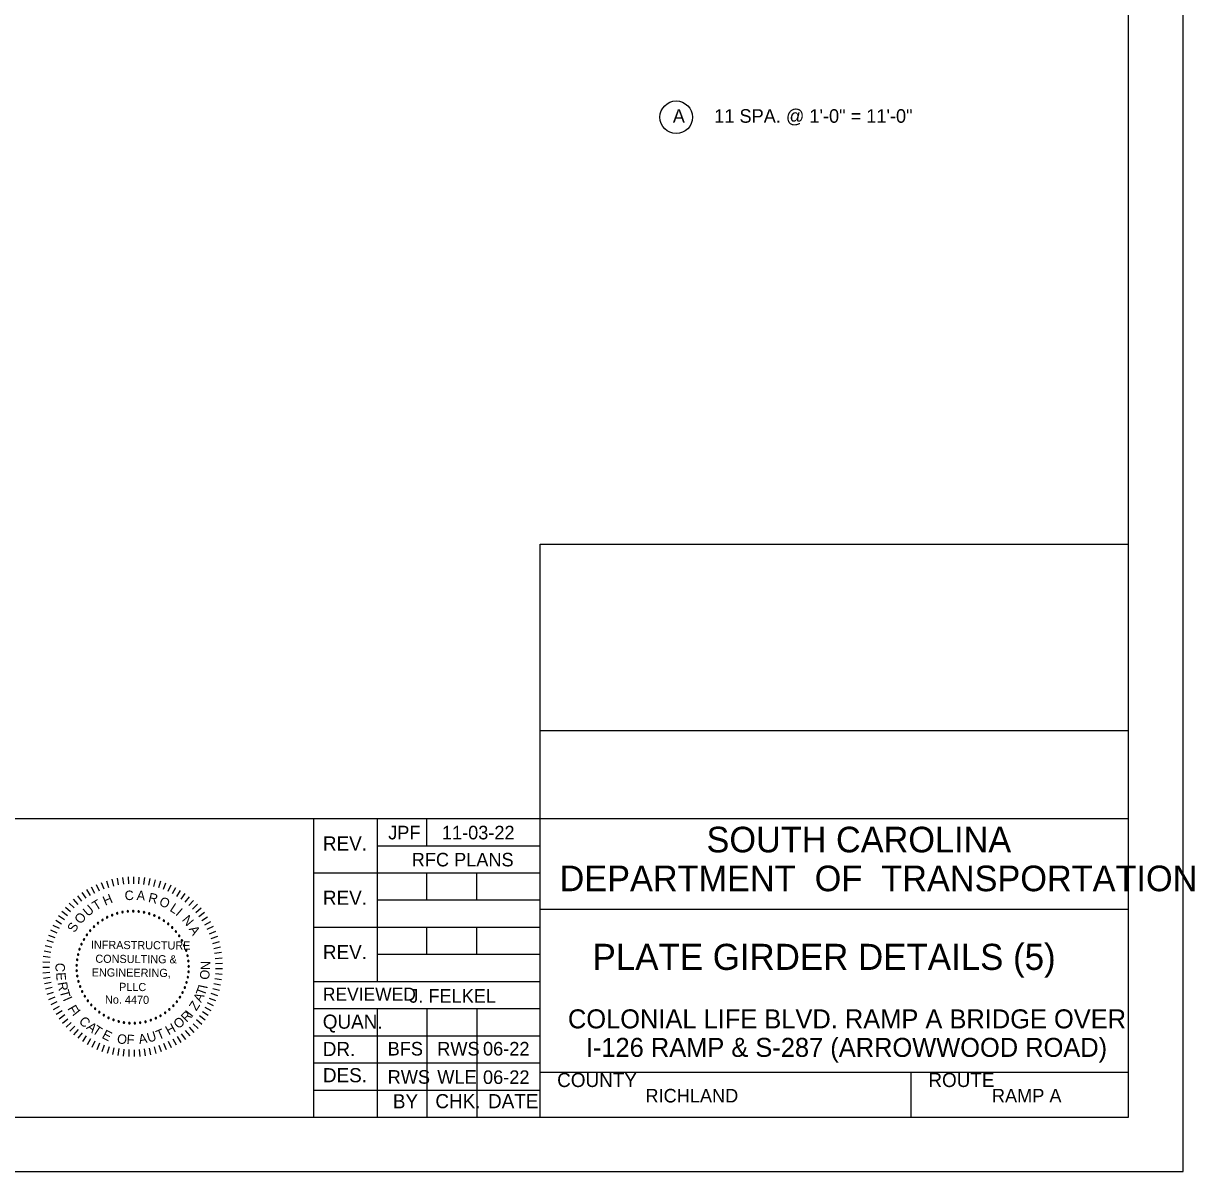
# Model space of a CAD drawing. Extents: x -383 to 14, y -392 to -94.
# Drawn here: x -203.87 to -160.75, y -187.49 to -145.21 of the extents above; entities that cross this region are included whole.
import ezdxf

# ---------------------------------------------------------------- set-up
doc = ezdxf.new("R2010")
doc.units = 0
for name, color, linetype in [('BR_BORDER LINES', 7, 'Continuous'), ('BR_TEXT', 7, 'Continuous'), ('Level 31', 7, 'Continuous')]:
    doc.layers.add(name, color=color, linetype=linetype)

msp = doc.modelspace()

# ---------------------------------------------------------------- linework, layer by layer
at = {"layer": 'BR_BORDER LINES'}
for p, q in [((-163.178, -185.489), (-163.178, -101.489)), ((-184.846, -185.489), (-184.846, -164.383)), ((-184.846, -164.383), (-163.178, -164.383)), ((-184.845, -171.242), (-163.178, -171.242)), ((-214.64, -174.489), (-193.18, -174.489)), ((-193.18, -185.489), (-193.18, -174.489)), ((-193.18, -174.489), (-163.178, -174.489)), ((-190.846, -174.489), (-190.846, -180.489)), ((-189.013, -175.489), (-189.013, -174.489)), ((-190.846, -175.489), (-184.846, -175.489)), ((-193.18, -176.489), (-184.846, -176.489)), ((-189.013, -177.489), (-189.013, -176.489)), ((-187.179, -177.489), (-187.179, -176.489)), ((-190.846, -177.489), (-184.846, -177.489)), ((-184.846, -177.822), (-184.846, -177.822)), ((-184.846, -177.823), (-163.178, -177.823)), ((-193.18, -178.489), (-184.846, -178.489)), ((-189.013, -179.489), (-189.013, -178.489)), ((-187.179, -179.489), (-187.179, -178.489)), ((-190.846, -179.489), (-184.846, -179.489)), ((-193.18, -180.489), (-184.846, -180.489)), ((-193.18, -181.489), (-184.846, -181.489)), ((-190.846, -181.489), (-190.846, -185.489)), ((-189.013, -181.489), (-189.013, -185.489)), ((-187.179, -181.489), (-187.179, -185.489)), ((-193.18, -182.489), (-184.846, -182.489)), ((-193.18, -183.489), (-184.846, -183.489)), ((-184.846, -183.823), (-163.178, -183.823)), ((-184.456, -183.823), (-163.178, -183.823)), ((-171.179, -185.489), (-171.179, -183.823)), ((-193.18, -184.489), (-184.846, -184.489)), ((-297.843, -185.489), (-163.178, -185.489))]:
    msp.add_line(p, q, dxfattribs=at)
at = {"layer": 'BR_TEXT'}
for p, q in [((-200.615, -176.726), (-200.555, -176.974)), ((-200.417, -176.685), (-200.373, -176.936)), ((-200.217, -176.656), (-200.188, -176.909)), ((-200.016, -176.64), (-200.002, -176.894)), ((-199.814, -176.636), (-199.816, -176.89)), ((-199.612, -176.644), (-199.63, -176.898)), ((-199.411, -176.664), (-199.444, -176.917)), ((-199.212, -176.697), (-199.26, -176.947)), ((-199.015, -176.741), (-199.079, -176.988)), ((-201.546, -177.106), (-201.415, -177.324)), ((-201.37, -177.007), (-201.252, -177.233)), ((-201.188, -176.92), (-201.084, -177.153)), ((-201.001, -176.844), (-200.912, -177.082)), ((-200.81, -176.779), (-200.735, -177.023)), ((-198.821, -176.798), (-198.9, -177.04)), ((-198.631, -176.866), (-198.724, -177.103)), ((-198.446, -176.946), (-198.553, -177.177)), ((-198.265, -177.037), (-198.387, -177.261)), ((-198.091, -177.139), (-198.226, -177.355)), ((-202.182, -177.601), (-202.002, -177.781)), ((-202.035, -177.463), (-201.866, -177.654)), ((-201.879, -177.334), (-201.723, -177.535)), ((-201.716, -177.215), (-201.572, -177.425)), ((-197.923, -177.251), (-198.071, -177.458)), ((-197.762, -177.373), (-197.922, -177.571)), ((-197.609, -177.505), (-197.781, -177.693)), ((-202.57, -178.065), (-202.36, -178.21)), ((-202.45, -177.903), (-202.25, -178.06)), ((-202.321, -177.748), (-202.13, -177.917)), ((-197.464, -177.646), (-197.647, -177.823)), ((-197.329, -177.795), (-197.522, -177.961)), ((-197.202, -177.952), (-197.405, -178.106)), ((-202.779, -178.411), (-202.553, -178.529)), ((-202.679, -178.235), (-202.461, -178.366)), ((-197.086, -178.117), (-197.298, -178.258)), ((-196.979, -178.289), (-197.199, -178.417)), ((-196.883, -178.467), (-197.111, -178.581)), ((-202.944, -178.779), (-202.705, -178.869)), ((-202.867, -178.593), (-202.634, -178.696)), ((-196.799, -178.65), (-197.033, -178.75)), ((-196.725, -178.838), (-196.965, -178.924)), ((-203.104, -179.363), (-202.853, -179.407)), ((-203.063, -179.165), (-202.815, -179.225)), ((-203.009, -178.97), (-202.766, -179.045)), ((-196.664, -179.03), (-196.908, -179.101)), ((-196.614, -179.226), (-196.862, -179.282)), ((-203.151, -179.764), (-202.897, -179.777)), ((-203.134, -179.562), (-202.881, -179.592)), ((-196.576, -179.424), (-196.827, -179.465)), ((-196.55, -179.625), (-196.804, -179.65)), ((-203.156, -179.965), (-202.901, -179.964)), ((-203.149, -180.167), (-202.895, -180.15)), ((-196.547, -180.23), (-196.8, -180.208)), ((-196.537, -179.826), (-196.791, -179.836)), ((-196.535, -180.028), (-196.79, -180.022)), ((-203.129, -180.368), (-202.877, -180.335)), ((-203.097, -180.568), (-202.847, -180.52)), ((-196.606, -180.629), (-196.855, -180.577)), ((-196.57, -180.43), (-196.822, -180.393)), ((-203.053, -180.765), (-202.807, -180.701)), ((-202.997, -180.959), (-202.755, -180.881)), ((-202.93, -181.149), (-202.693, -181.056)), ((-196.713, -181.018), (-196.954, -180.936)), ((-196.653, -180.825), (-196.899, -180.758)), ((-202.851, -181.335), (-202.62, -181.228)), ((-202.761, -181.516), (-202.536, -181.395)), ((-196.96, -181.57), (-197.182, -181.446)), ((-196.867, -181.392), (-197.096, -181.281)), ((-196.784, -181.207), (-197.02, -181.111)), ((-202.66, -181.69), (-202.443, -181.556)), ((-202.548, -181.859), (-202.34, -181.711)), ((-202.426, -182.02), (-202.228, -181.86)), ((-197.304, -182.068), (-197.5, -181.905)), ((-197.179, -181.91), (-197.385, -181.759)), ((-197.065, -181.743), (-197.279, -181.605)), ((-202.295, -182.173), (-202.107, -182.002)), ((-202.155, -182.319), (-201.977, -182.136)), ((-202.006, -182.455), (-201.84, -182.262)), ((-201.849, -182.582), (-201.695, -182.379)), ((-197.733, -182.495), (-197.895, -182.3)), ((-197.581, -182.362), (-197.756, -182.176)), ((-197.438, -182.219), (-197.623, -182.045)), ((-201.685, -182.699), (-201.543, -182.487)), ((-201.513, -182.806), (-201.385, -182.586)), ((-201.336, -182.903), (-201.221, -182.675)), ((-201.153, -182.988), (-201.053, -182.754)), ((-198.596, -183.012), (-198.692, -182.777)), ((-198.411, -182.93), (-198.522, -182.701)), ((-198.232, -182.837), (-198.356, -182.615)), ((-198.059, -182.734), (-198.196, -182.519)), ((-197.892, -182.62), (-198.042, -182.414)), ((-200.965, -183.062), (-200.879, -182.822)), ((-200.773, -183.125), (-200.702, -182.88)), ((-200.577, -183.175), (-200.521, -182.927)), ((-200.379, -183.214), (-200.338, -182.962)), ((-200.179, -183.24), (-200.154, -182.987)), ((-199.978, -183.254), (-199.968, -183)), ((-199.776, -183.256), (-199.781, -183.002)), ((-199.574, -183.246), (-199.595, -182.992)), ((-199.373, -183.223), (-199.41, -182.971)), ((-199.174, -183.188), (-199.226, -182.939)), ((-198.978, -183.142), (-199.045, -182.896)), ((-198.785, -183.083), (-198.867, -182.842))]:
    msp.add_line(p, q, dxfattribs=at)
msp.add_circle((-179.834, -148.668), 0.6, dxfattribs=at)
for centre, start, end in [((-200.603, -178.045), 21.6807, 201.6807), ((-200.603, -178.045), 201.6807, 21.6807), ((-200.414, -177.98), 16.1422, 196.1422), ((-200.414, -177.98), 196.1422, 16.1422), ((-200.22, -177.935), 10.6038, 190.6038), ((-200.22, -177.935), 190.6038, 10.6038), ((-200.023, -177.908), 5.0653, 185.0653), ((-200.023, -177.908), 185.0653, 5.0653), ((-199.824, -177.9), 359.5268, 179.5268), ((-199.824, -177.9), 179.5268, 359.5268), ((-199.625, -177.912), 353.9884, 173.9884), ((-199.625, -177.912), 173.9884, 353.9884), ((-199.428, -177.943), 168.4499, 348.4499), ((-199.428, -177.943), 348.4499, 168.4499), ((-199.235, -177.992), 162.9114, 342.9114), ((-199.235, -177.992), 342.9114, 162.9114), ((-199.047, -178.06), 157.373, 337.373), ((-199.047, -178.06), 337.373, 157.373), ((-201.27, -178.472), 43.8345, 223.8345), ((-201.27, -178.472), 223.8345, 43.8345), ((-201.12, -178.341), 38.2961, 218.2961), ((-201.12, -178.341), 218.2961, 38.2961), ((-200.957, -178.226), 32.7576, 212.7576), ((-200.957, -178.226), 212.7576, 32.7576), ((-200.785, -178.127), 27.2191, 207.2191), ((-200.785, -178.127), 207.2191, 27.2191), ((-198.867, -178.146), 151.8345, 331.8345), ((-198.867, -178.146), 331.8345, 151.8345), ((-198.697, -178.249), 146.2961, 326.2961), ((-198.697, -178.249), 326.2961, 146.2961), ((-198.537, -178.368), 140.7576, 320.7576), ((-198.537, -178.368), 320.7576, 140.7576), ((-198.389, -178.502), 135.2191, 315.2191), ((-198.389, -178.502), 315.2191, 135.2191), ((-201.637, -178.942), 60.4499, 240.4499), ((-201.637, -178.942), 240.4499, 60.4499), ((-201.53, -178.774), 54.9114, 234.9114), ((-201.53, -178.774), 234.9114, 54.9114), ((-201.408, -178.617), 49.373, 229.373), ((-201.408, -178.617), 229.373, 49.373), ((-198.255, -178.649), 129.6807, 309.6807), ((-198.255, -178.649), 309.6807, 129.6807), ((-198.135, -178.809), 124.1422, 304.1422), ((-198.135, -178.809), 304.1422, 124.1422), ((-201.8, -179.305), 71.5268, 251.5268), ((-201.8, -179.305), 251.5268, 71.5268), ((-201.727, -179.12), 65.9884, 245.9884), ((-201.727, -179.12), 245.9884, 65.9884), ((-198.032, -178.979), 118.6038, 298.6038), ((-198.032, -178.979), 298.6038, 118.6038), ((-197.945, -179.159), 113.0653, 293.0653), ((-197.945, -179.159), 293.0653, 113.0653), ((-197.876, -179.346), 107.5268, 287.5268), ((-197.876, -179.346), 287.5268, 107.5268), ((-201.89, -179.693), 82.6038, 262.6038), ((-201.89, -179.693), 262.6038, 82.6038), ((-201.854, -179.497), 77.0653, 257.0653), ((-201.854, -179.497), 257.0653, 77.0653), ((-197.826, -179.538), 101.9884, 281.9884), ((-197.826, -179.538), 281.9884, 101.9884), ((-197.795, -179.735), 96.4499, 276.4499), ((-197.795, -179.735), 276.4499, 96.4499), ((-201.906, -179.892), 88.1422, 268.1422), ((-201.904, -180.091), 93.6807, 273.6807), ((-201.906, -179.892), 268.1422, 88.1422), ((-201.904, -180.091), 273.6807, 93.6807), ((-197.789, -180.133), 85.373, 265.373), ((-197.782, -179.934), 90.9114, 270.9114), ((-197.789, -180.133), 265.373, 85.373), ((-197.782, -179.934), 270.9114, 90.9114), ((-201.882, -180.289), 99.2191, 279.2191), ((-201.882, -180.289), 279.2191, 99.2191), ((-201.841, -180.484), 104.7576, 284.7576), ((-201.841, -180.484), 284.7576, 104.7576), ((-201.781, -180.675), 110.2961, 290.2961), ((-201.781, -180.675), 290.2961, 110.2961), ((-197.86, -180.525), 74.2961, 254.2961), ((-197.86, -180.525), 254.2961, 74.2961), ((-197.815, -180.331), 79.8345, 259.8345), ((-197.815, -180.331), 259.8345, 79.8345), ((-201.703, -180.858), 115.8345, 295.8345), ((-201.703, -180.858), 295.8345, 115.8345), ((-201.608, -181.033), 121.373, 301.373), ((-201.608, -181.033), 301.373, 121.373), ((-198.104, -181.069), 57.6807, 237.6807), ((-198.104, -181.069), 237.6807, 57.6807), ((-198.005, -180.896), 63.2191, 243.2191), ((-198.005, -180.896), 243.2191, 63.2191), ((-197.924, -180.714), 68.7576, 248.7576), ((-197.924, -180.714), 248.7576, 68.7576), ((-201.497, -181.199), 126.9114, 306.9114), ((-201.497, -181.199), 306.9114, 126.9114), ((-201.37, -181.352), 132.4499, 312.4499), ((-201.37, -181.352), 312.4499, 132.4499), ((-201.228, -181.493), 137.9884, 317.9884), ((-201.228, -181.493), 317.9884, 137.9884), ((-198.493, -181.521), 41.0653, 221.0653), ((-198.493, -181.521), 221.0653, 41.0653), ((-198.349, -181.383), 46.6038, 226.6038), ((-198.349, -181.383), 226.6038, 46.6038), ((-198.219, -181.232), 52.1422, 232.1422), ((-198.219, -181.232), 232.1422, 52.1422), ((-201.074, -181.619), 143.5268, 323.5268), ((-201.074, -181.619), 323.5268, 143.5268), ((-200.909, -181.73), 149.0653, 329.0653), ((-200.909, -181.73), 329.0653, 149.0653), ((-200.733, -181.825), 154.6038, 334.6038), ((-200.733, -181.825), 334.6038, 154.6038), ((-200.549, -181.902), 160.1422, 340.1422), ((-200.549, -181.902), 340.1422, 160.1422), ((-200.359, -181.961), 345.6807, 165.6807), ((-199.372, -181.971), 13.373, 193.373), ((-199.18, -181.916), 18.9114, 198.9114), ((-199.18, -181.916), 198.9114, 18.9114), ((-198.995, -181.842), 24.4499, 204.4499), ((-198.995, -181.842), 204.4499, 24.4499), ((-198.817, -181.752), 29.9884, 209.9884), ((-198.817, -181.752), 209.9884, 29.9884), ((-198.649, -181.644), 35.5268, 215.5268), ((-198.649, -181.644), 215.5268, 35.5268), ((-200.359, -181.961), 165.6807, 345.6807), ((-200.164, -182.001), 171.2191, 351.2191), ((-200.164, -182.001), 351.2191, 171.2191), ((-199.965, -182.022), 176.7576, 356.7576), ((-199.965, -182.022), 356.7576, 176.7576), ((-199.766, -182.024), 2.2961, 182.2961), ((-199.766, -182.024), 182.2961, 2.2961), ((-199.568, -182.007), 7.8345, 187.8345), ((-199.568, -182.007), 187.8345, 7.8345), ((-199.372, -181.971), 193.373, 13.373)]:
    msp.add_arc(centre, 0.028, start, end, dxfattribs=at)
at = {"layer": 'Level 31'}
msp.add_line((-174.011, -179.583), (-174.011, -179.583), dxfattribs=at)
msp.add_lwpolyline([(-305.176, -187.489), (-161.176, -187.489), (-161.176, -99.489), (-305.176, -99.489)], close=True, dxfattribs=at)

# ---------------------------------------------------------------- texts
at = {"layer": 'BR_TEXT'}
for s, height, rotation, p in [('A', 0.5, 360, (-179.96, -148.871)), ('C', 0.349, 4.7281, (-200.126, -177.506)), ('A', 0.349, 355.6981, (-199.708, -177.486)), ('T', 0.349, 31.8182, (-201.196, -177.894)), ('H', 0.349, 22.7882, (-200.857, -177.704)), ('R', 0.349, 346.6681, (-199.291, -177.554)), ('O', 0.349, 337.638, (-198.9, -177.673)), ('L', 0.349, 327.108, (-198.504, -177.875)), ('O', 0.349, 49.8782, (-201.757, -178.403)), ('U', 0.349, 40.8482, (-201.49, -178.119)), ('I', 0.349, 319.578, (-198.294, -178.026)), ('N', 0.349, 310.548, (-198.051, -178.23)), ('S', 0.349, 58.9083, (-201.979, -178.715)), ('A', 0.349, 301.5179, (-197.791, -178.559)), ('INFRASTRUCTURE', 0.29909, 359.5268, (-201.385, -179.286)), ('CONSULTING &', 0.29909, 359.5268, (-201.22, -179.8)), ('N', 0.349, 89.2085, (-196.993, -180.074)), ('C', 0.349, 267.025, (-202.679, -179.795)), ('E', 0.349, 273.025, (-202.662, -180.161)), ('ENGINEERING,', 0.29909, 359.5268, (-201.354, -180.302)), ('O', 0.349, 83.2085, (-197.038, -180.44)), ('R', 0.349, 279.025, (-202.61, -180.531)), ('PLLC', 0.2991, 359.5268, (-200.347, -180.836)), ('I', 0.349, 77.9093, (-197.1, -180.777)), ('T', 0.349, 285.025, (-202.541, -180.846)), ('I', 0.349, 293.7713, (-202.422, -181.138)), ('No. 4470', 0.2991, 359.5268, (-200.865, -181.304)), ('A', 0.349, 63.3954, (-197.326, -181.288)), ('T', 0.349, 69.3954, (-197.203, -181.047)), ('F', 0.349, 299.7713, (-202.257, -181.482)), ('I', 0.349, 308.5268, (-202.089, -181.698)), ('Z', 0.349, 57.3954, (-197.501, -181.594)), ('C', 0.349, 314.5268, (-201.851, -181.978)), ('O', 0.349, 38.5268, (-198.169, -182.254)), ('R', 0.349, 44.5268, (-197.863, -182.014)), ('I', 0.349, 52.3339, (-197.665, -181.825)), ('A', 0.349, 320.5268, (-201.575, -182.213)), ('T', 0.349, 326.5268, (-201.357, -182.366)), ('E', 0.349, 332.5268, (-201.003, -182.558)), ('U', 0.349, 16.5268, (-199.261, -182.742)), ('T', 0.349, 22.5268, (-198.894, -182.645)), ('H', 0.349, 28.5268, (-198.522, -182.478)), ('O', 0.349, 350.5268, (-200.442, -182.753)), ('F', 0.349, 356.5268, (-200.076, -182.79)), ('A', 0.349, 10.5268, (-199.597, -182.796))]:
    msp.add_text(s, height=height, rotation=rotation, dxfattribs=at).set_placement(p)
for s, height, p in [('11 SPA. @ 1\'-0" = 11\'-0"', 0.5, (-178.434, -148.871)), ('JPF', 0.5, (-190.438, -175.257)), ('11-03-22', 0.5, (-188.461, -175.257)), ('SOUTH CAROLINA', 0.94348, (-178.718, -175.735)), ('REV.', 0.52, (-192.841, -175.667)), ('RFC PLANS', 0.5, (-189.572, -176.253)), ('DEPARTMENT  OF  TRANSPORTATION', 0.94348, (-184.129, -177.166)), ('REV.', 0.52, (-192.841, -177.667)), ('REV.', 0.52, (-192.841, -179.667)), ('PLATE GIRDER DETAILS (5)', 0.96, (-182.913, -180.063)), ('REVIEWED', 0.48, (-192.843, -181.195)), ('J. FELKEL', 0.5, (-189.664, -181.272)), ('COLONIAL LIFE BLVD. RAMP A BRIDGE OVER', 0.7, (-183.82, -182.216)), ('QUAN.', 0.52, (-192.846, -182.229)), ('DR.', 0.52, (-192.845, -183.235)), ('BFS', 0.5, (-190.457, -183.215)), ('RWS', 0.5, (-188.632, -183.215)), ('06-22', 0.5, (-186.946, -183.215)), ('I-126 RAMP & S-287 (ARROWWOOD ROAD)', 0.7, (-183.162, -183.266)), ('DES.', 0.52, (-192.841, -184.2)), ('RWS', 0.5, (-190.457, -184.254)), ('WLE', 0.5, (-188.63, -184.254)), ('06-22', 0.5, (-186.946, -184.263)), ('COUNTY', 0.52, (-184.217, -184.376)), ('ROUTE', 0.52, (-170.55, -184.376)), ('RICHLAND', 0.5, (-180.968, -184.944)), ('RAMP A', 0.5, (-168.212, -184.944)), ('BY', 0.52, (-190.265, -185.161)), ('CHK.', 0.52, (-188.701, -185.156)), ('DATE', 0.52, (-186.761, -185.156))]:
    msp.add_text(s, height=height, dxfattribs=at).set_placement(p)

doc.saveas('drawing.dxf')
